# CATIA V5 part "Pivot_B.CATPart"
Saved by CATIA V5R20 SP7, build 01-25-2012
Part number: Pivot_B
Bounding box of the stored display mesh (mm): x 72.5 to 77.5, y 107.5 to 112.5, z -50 to -38
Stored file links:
  D:\IFMA\COURS\2A\projet balance IAO\catia\Pivot_B.CATPart
  D:\IFMA\COURS\2A\projet balance IAO\catia\Ass_projet_balance.CATProduct
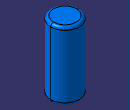
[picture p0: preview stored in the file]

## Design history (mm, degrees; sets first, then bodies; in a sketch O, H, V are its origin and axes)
Set1
  Plane1 "Plan_BC": linked copy from another document
  Point1 "Point.B": linked copy from another document
  Plane2 "Plan_socle_3": linked copy from another document
Body1 (main body)
  Sketch1 on Plane2, origin (0, 0, -50), H (1, 0, 0), V (0, 1, 0)
    circle A1 centre (75, 110) radius 2.5
    point P1 (75, 110)
    reference projected point E1 (75, 110) from Point1
    radius A1 = 2.5
    coincidence: P1 E1
  Pad1: profile Sketch1, direction (0, 0, 1), length 12
  Fillet1: radius 0.5, on edge [face of Pad1 from Sketch1.A1 | end face of Pad1]; edge [start face of Pad1 | face of Pad1 from Sketch1.A1]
